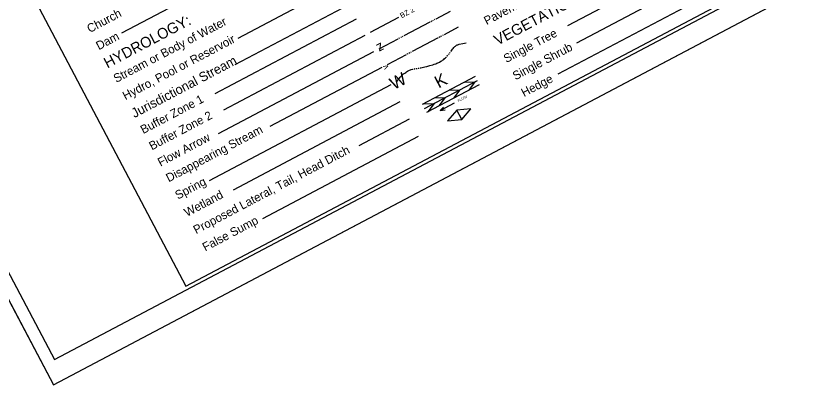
# Model space of a CAD drawing. Extents: x 1487118 to 1489121, y 496367 to 498126.
# Drawn here: x 1487593 to 1488418, y 496367 to 496745 of the extents above; entities that cross this region are included whole.
import ezdxf

# ---------------------------------------------------------------- set-up
doc = ezdxf.new("R2010")
doc.units = 0
for name, color, linetype in [('Sheet Cutting Line CELL', 7, 'Continuous'), ('Sheet Plot Border Inside CELL', 7, 'Continuous'), ('Sheet Plot Border Outside CELL', 7, 'Continuous'), ('Sheet Symbology CELL', 7, 'Continuous')]:
    doc.layers.add(name, color=color, linetype=linetype)

msp = doc.modelspace()

# ---------------------------------------------------------------- linework, layer by layer
at = {"layer": 'Sheet Cutting Line CELL'}
for p, q in [((1487118.01, 497340.04), (1487631.63, 496367.31)), ((1487631.63, 496367.31), (1489120.78, 497153.62))]:
    msp.add_line(p, q, dxfattribs=at)
at = {"layer": 'Sheet Plot Border Inside CELL'}
msp.add_lwpolyline([(1487632.64, 496393.24), (1489106.32, 497171.37), (1488613.66, 498104.39), (1487139.99, 497326.26)], close=True, dxfattribs=at)
at = {"layer": 'Sheet Plot Border Outside CELL'}
msp.add_lwpolyline([(1487631.63, 496367.31), (1489120.78, 497153.62), (1488607.16, 498126.35), (1487118.01, 497340.04)], close=True, dxfattribs=at)
at = {"layer": 'Sheet Symbology CELL'}
for p, q in [((1487900.7, 496832.42), (1487701.36, 496727.17)), ((1488317.85, 496819.32), (1488157.68, 496734.75)), ((1488327.18, 496801.63), (1488167.02, 496717.06)), ((1488335.94, 496784.48), (1488147.86, 496685.17)), ((1487923.27, 496776.27), (1487820.35, 496721.92)), ((1487933.82, 496756.29), (1487817.44, 496694.84)), ((1488023.35, 496742.09), (1488037.92, 496749.78)), ((1487941.58, 496741.59), (1487796.77, 496665.13)), ((1487956, 496728.23), (1487985, 496743.55)), ((1488021.58, 496741.16), (1488022.46, 496741.62)), ((1487990.63, 496724.81), (1488017.16, 496738.82)), ((1488018.04, 496739.29), (1488018.93, 496739.75)), ((1488019.81, 496740.22), (1488020.69, 496740.69)), ((1488031.81, 496726.07), (1488046.38, 496733.76)), ((1487950.39, 496724.91), (1487805.59, 496648.45)), ((1488028.27, 496724.2), (1488029.15, 496724.67)), ((1488030.04, 496725.13), (1488030.92, 496725.6)), ((1487964.96, 496711.26), (1487984.44, 496721.54)), ((1487985.32, 496722.01), (1487986.21, 496722.48)), ((1487987.09, 496722.94), (1487987.98, 496723.41)), ((1487988.86, 496723.88), (1487989.74, 496724.35)), ((1487999.09, 496708.79), (1488025.62, 496722.8)), ((1488026.5, 496723.27), (1488027.39, 496723.73)), ((1487959.2, 496708.22), (1487800.17, 496624.25)), ((1487997.32, 496707.86), (1487998.2, 496708.32)), ((1487973.42, 496695.24), (1487992.9, 496705.52)), ((1487993.78, 496705.99), (1487994.67, 496706.46)), ((1487995.55, 496706.92), (1487996.44, 496707.39)), ((1488034.69, 496703.87), (1488035.34, 496704.64)), ((1488035.99, 496705.39), (1488036.62, 496706.16)), ((1487967.66, 496692.2), (1487853.14, 496631.72)), ((1488004.85, 496691.42), (1488005.84, 496691.58)), ((1488009.53, 496654.65), (1488063.48, 496683.14)), ((1488011.53, 496650.28), (1488065.72, 496678.89)), ((1488052.24, 496677.2), (1488062.97, 496677.44)), ((1488062.97, 496677.44), (1488056.88, 496668.97)), ((1487977, 496674.51), (1487790.88, 496576.24)), ((1488013.94, 496646.29), (1488067.89, 496674.78)), ((1488036.55, 496668.92), (1488047.48, 496669.26)), ((1488047.48, 496669.26), (1488041.27, 496660.73)), ((1488021.56, 496661.01), (1488032.46, 496661.33)), ((1488032.46, 496661.33), (1488026.25, 496652.8)), ((1487986.34, 496656.83), (1487815.48, 496566.61)), ((1488010.32, 496655.07), (1488021.22, 496655.4)), ((1488021.22, 496655.4), (1488014.98, 496646.84)), ((1488027.31, 496648.27), (1488042.04, 496656.04)), ((1488027.31, 496648.27), (1488030.93, 496651.7)), ((1488027.31, 496648.27), (1488032.47, 496648.78)), ((1488044.44, 496648.62), (1488034.9, 496637.62)), ((1488058.8, 496649.95), (1488044.44, 496648.62)), ((1488049.6, 496638.85), (1488044.44, 496648.62)), ((1488049.6, 496638.85), (1488058.8, 496649.95)), ((1487995.68, 496639.14), (1487944.23, 496611.98)), ((1488034.9, 496637.62), (1488049.6, 496638.85)), ((1488005.02, 496621.45), (1487845.6, 496537.28))]:
    msp.add_line(p, q, dxfattribs=at)
msp.add_lwpolyline([(1488603.8, 498096.3), (1487277.36, 497395.91), (1487767.16, 496468.3), (1489093.6, 497168.69)], close=True, dxfattribs=at)
for points in [[(1488038.46, 496708.55), (1488038.77, 496708.98), (1488040.02, 496710.8), (1488040.68, 496711.7), (1488041.4, 496712.56), (1488041.97, 496713.16), (1488042.51, 496713.64), (1488043.01, 496714.04), (1488043.45, 496714.38), (1488044.28, 496714.89), (1488044.92, 496715.23), (1488045.42, 496715.44), (1488046.18, 496715.72), (1488046.96, 496715.93), (1488050.55, 496716.73), (1488054.14, 496717.5)], [(1488006.84, 496691.74), (1488007.63, 496691.86), (1488009.06, 496692.15), (1488011.77, 496692.77), (1488013.8, 496693.27), (1488016.82, 496694.06), (1488019.82, 496694.93), (1488021.46, 496695.46), (1488022.9, 496695.96), (1488024.14, 496696.45), (1488025.21, 496696.9), (1488026.13, 496697.33), (1488026.94, 496697.73), (1488028.3, 496698.47), (1488029.29, 496699.08), (1488030.02, 496699.58), (1488031.07, 496700.35), (1488032.07, 496701.19), (1488032.8, 496701.87), (1488033.42, 496702.48), (1488034.02, 496703.14)], [(1488037.26, 496706.94), (1488037.39, 496707.11), (1488037.87, 496707.73)], [(1487982.77, 496677.56), (1487984.73, 496679.93), (1487986.69, 496682.33), (1487987.19, 496682.9), (1487988.1, 496683.88), (1487988.84, 496684.57), (1487989.97, 496685.55), (1487991.16, 496686.47), (1487992.18, 496687.18), (1487993.11, 496687.77), (1487993.95, 496688.24), (1487994.7, 496688.64), (1487996.06, 496689.25), (1487997.1, 496689.67), (1487997.88, 496689.95), (1487999.09, 496690.32), (1487999.93, 496690.54)], [(1488000.92, 496690.76), (1488001.39, 496690.85), (1488001.89, 496690.95)], [(1488002.88, 496691.12), (1488003.31, 496691.19), (1488003.87, 496691.27)]]:
    msp.add_lwpolyline(points, dxfattribs=at)

# ---------------------------------------------------------------- texts
for s, height, rotation, p in [('Pavement Removal', 8.75, 27.83509, (1488075.09, 496735.36)), ('VEGETATION:', 11, 27.83509, (1488086.12, 496714.43)), ('Church', 8.75, 27.83509, (1487668.82, 496727.29)), ('BZ 2', 5.315, 27.83509, (1487988.04, 496742.4)), ('HYDROLOGY:', 11, 27.83509, (1487686.84, 496691.03)), ('Stream or Body of Water', 8.75, 27.83509, (1487695.92, 496676.28)), ('Dam', 8.75, 27.83509, (1487678.06, 496709.76)), ('Single Tree', 8.75, 27.83509, (1488095.2, 496696.64)), ('Hydro, Pool or Reservoir', 8.75, 27.83509, (1487705.25, 496658.59)), ('z', 10, 207.83511, (1487967.06, 496718.02)), ('Single Shrub', 8.75, 27.83509, (1488104.54, 496678.96)), ('Jurisdictional Stream', 9.646, 27.83509, (1487714.54, 496640.28)), ('v', 6.6, 117.59424, (1487975.17, 496691.93)), ('W', 12.75, 27.83509, (1487980.11, 496668.94)), ('K', 12.75, 27.83509, (1488025.93, 496670.52)), ('Hedge', 8.75, 27.83509, (1488113.3, 496661.8)), ('Buffer Zone 1', 8.75, 27.83509, (1487723.56, 496623.92)), ('FLOW', 2.593, 27.83509, (1488046.15, 496656.69)), ('Buffer Zone 2', 8.75, 27.83509, (1487732.37, 496607.23)), ('Disappearing Stream', 8.75, 27.83509, (1487749.65, 496574.52)), ('Flow Arrow', 8.75, 27.83509, (1487741.19, 496590.54)), ('Proposed Lateral, Tail, Head Ditch', 8.75, 27.83509, (1487777.66, 496521.46)), ('Spring', 8.75, 27.83509, (1487758.98, 496556.84)), ('Wetland', 8.75, 27.83509, (1487768.32, 496539.15)), ('False Sump', 8.75, 27.83509, (1487787, 496503.78))]:
    msp.add_text(s, height=height, rotation=rotation, dxfattribs=at).set_placement(p)

doc.saveas('drawing.dxf')
